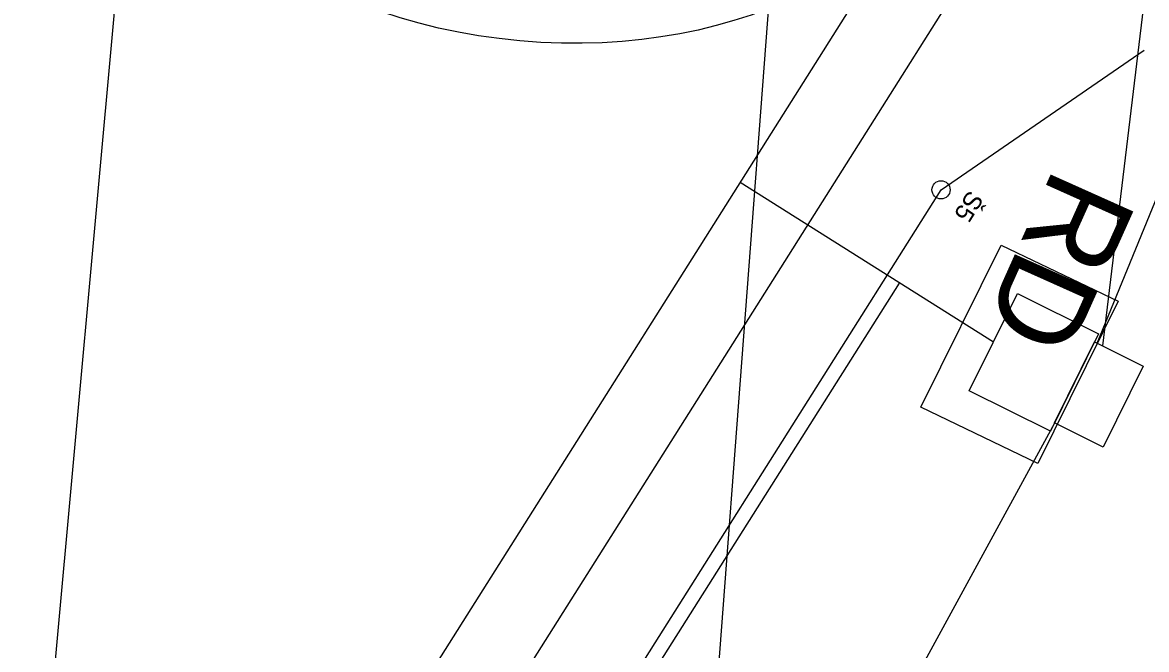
# Model space of a CAD drawing. Extents: x -743359 to -742769, y -1127804 to -1126284.
# Drawn here: x -743182.74 to -743151.71, y -1127088.87 to -1127071.55 of the extents above; entities that cross this region are included whole.
import ezdxf

# ---------------------------------------------------------------- set-up
doc = ezdxf.new("R2010")
doc.units = 0
for name, color, linetype in [('_TRASA_vedení kabelu_CEZ', 7, 'Continuous'), ('_Zabezpečovací zařízení_trasa', 7, 'Continuous'), ('bublina_fialová_čára_tenká', 7, 'Continuous'), ('bublina_růžová_230_čára_tučná', 7, 'Continuous'), ('Default', 7, 'Continuous'), ('SMER_VYS_VYROVNANI', 7, 'Continuous'), ('TRATIVOD', 7, 'Continuous')]:
    doc.layers.add(name, color=color, linetype=linetype)

msp = doc.modelspace()

# ---------------------------------------------------------------- linework, layer by layer
at = {"layer": '_TRASA_vedení kabelu_CEZ'}
for points in [[(-743153.07, -1127080.408), (-743148.258, -1127068.653), (-743137.261, -1127046.755), (-743132.067, -1127038.676)], [(-743154.255, -1127082.611), (-743159.254, -1127091.791), (-743078.983, -1127101.896), (-743017.042, -1127110.608), (-742993.931, -1127114.824), (-742964.817, -1127120.763), (-742937.743, -1127126.541), (-742940.646, -1127140.696), (-742942.997, -1127146.397)]]:
    msp.add_lwpolyline(points, dxfattribs=at)
msp.add_lwpolyline([(-743154.256, -1127082.61), (-743153.145, -1127080.371), (-743151.801, -1127081.038), (-743152.912, -1127083.277)], close=True, dxfattribs=at)
at = {"layer": '_Zabezpečovací zařízení_trasa'}
msp.add_line((-743155.94, -1127080.38), (-743162.932, -1127075.966), dxfattribs=at)
for points in [[(-743098.647, -1126974.146), (-743125.94, -1127017.384), (-743152.604, -1127059.608), (-743175.023, -1127095.116), (-743199.163, -1127133.346), (-743215.971, -1127159.941), (-743232.818, -1127186.515), (-743247.456, -1127209.811), (-743254.52, -1127221.639), (-743261.299, -1127233.691), (-743264.155, -1127239.195), (-743264.862, -1127241.108), (-743267.337, -1127245.816), (-743268.289, -1127247.159), (-743271.711, -1127253.75), (-743281.122, -1127274.196), (-743291.923, -1127301.42), (-743296.724, -1127315.222), (-743301.116, -1127329.128), (-743306.787, -1127349.506), (-743311.536, -1127370.056), (-743315.693, -1127392.87), (-743318.79, -1127415.837)], [(-743164.036, -1127096.193), (-743163.862, -1127095.231), (-743167.492, -1127092.937), (-743158.53, -1127078.745)]]:
    msp.add_lwpolyline(points, dxfattribs=at)
at = {"layer": 'bublina_fialová_čára_tenká'}
for p, q in [((-743145.088, -1127015.481), (-743152.928, -1127080.479)), ((-743160.679, -1127051.634), (-743164.286, -1127099.423)), ((-743179.562, -1127064.096), (-743182.5, -1127096.45))]:
    msp.add_line(p, q, dxfattribs=at)
at = {"layer": 'bublina_růžová_230_čára_tučná'}
msp.add_ellipse((-743168.337, -1127064.588), major_axis=(-11.205, 1.008), ratio=0.666667, dxfattribs=at)
at = {"layer": 'Default'}
for points in [[(-743157.946, -1127082.176), (-743155.726, -1127077.696), (-743152.496, -1127079.25), (-743154.716, -1127083.73)], [(-743156.606, -1127081.724), (-743155.274, -1127079.036), (-743153.034, -1127080.146), (-743154.366, -1127082.834)]]:
    msp.add_lwpolyline(points, close=True, dxfattribs=at)
at = {"layer": 'SMER_VYS_VYROVNANI'}
msp.add_lwpolyline([(-743143.427, -1127049.192), (-743169.53, -1127090.542)], dxfattribs=at)
at = {"layer": 'TRATIVOD'}
msp.add_line((-743157.384, -1127076.172), (-743151.775, -1127072.311), dxfattribs=at)
msp.add_lwpolyline([(-743175.637, -1127105.086), (-743168.399, -1127093.621), (-743157.384, -1127076.172), (-743151.775, -1127072.311)], dxfattribs=at)
msp.add_circle((-743157.384, -1127076.172), 0.25, dxfattribs=at)

# ---------------------------------------------------------------- texts
at = {"layer": 'Default'}
msp.add_text('RD', height=2.5, rotation=245.8595, dxfattribs=at).set_placement((-743154.246, -1127075.497))
at = {"layer": 'TRATIVOD'}
msp.add_text('Š5', height=0.5, rotation=238, dxfattribs=at).set_placement((-743156.61, -1127076.155))

doc.saveas('drawing.dxf')
